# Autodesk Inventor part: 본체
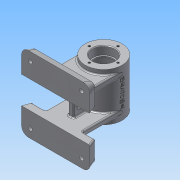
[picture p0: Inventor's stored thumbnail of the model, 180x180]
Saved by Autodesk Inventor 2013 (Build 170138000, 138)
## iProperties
Created: 2016-07
Part Number: 본체
Material: 알루미늄 6061
Document SubType Name: Modeling
Designer: Administrator
Density: 1 g/cm^3
Author: Administrator
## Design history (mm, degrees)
sketch "스케치1"
  geometry: L1 (40, -55)-(-40, -55); L2 (-50, -45)-(-50, 45); L3 (-40, 55)-(40, 55); L4 (50, 45)-(50, -45); L5 (50, -55)-(-50, 55); L6 (-50, -55)-(50, 55); A1 r 10 centre (-40, 45) between (-40, 55) and (-50, 45); A2 r 10 centre (40, 45) between (50, 45) and (40, 55); A3 r 10 centre (40, -45) between (40, -55) and (50, -45); A4 r 10 centre (-40, -45) between (-50, -45) and (-40, -55); 1 further point
  constraints: 12 end point, 8 point on circle, 8 point on line, 8 tangent, 4 centre point, 3 equal radius, 2 midpoint, 2 parallel, 1 horizontal, 1 perpendicular
  dimensions: "d0" = 100 distance of L5.end L6.end; "d1" = 110 distance of L6.start L5.end; "d8" = 10 radius of A1
node "작업 평면1"
sketch "스케치2"
  geometry: L1 (-40.632, 50.632)-(40.632, 50.632); L2 (45.632, 45.632)-(45.632, -45.632); L3 (40.632, -50.632)-(-40.632, -50.632); L4 (-45.632, -45.632)-(-45.632, 45.632); A1 r 5 centre (-40.632, 45.632) between (-40.632, 50.632) and (-45.632, 45.632); A2 r 5 centre (-40.632, -45.632) between (-45.632, -45.632) and (-40.632, -50.632); A3 r 5 centre (40.632, -45.632) between (40.632, -50.632) and (45.632, -45.632); A4 r 5 centre (40.632, 45.632) between (45.632, 45.632) and (40.632, 50.632); 4 further points
  constraints: 8 end point, 8 point on circle, 8 tangent, 6 point on line, 4 centre point, 3 equal radius, 2 parallel, 1 horizontal, 1 perpendicular
  dimensions: "d9" = 5 radius of A1
feature "로프트1" sketch "스케치2" dims "d4" = 0, "d5" = 90 deg, "d6" = 0, "d7" = 90 deg
sketch "스케치3"
  geometry: L1 (-9.368, 5.632)-(-9.368, 95.632) reference; L2 (90.632, 95.632)-(90.632, 5.632) reference; L3 (90.632, 30.632)-(-9.368, 30.632); L4 (-9.368, 30.632)-(-9.368, 70.632); L5 (-9.368, 70.632)-(90.632, 70.632); L6 (90.632, 70.632)-(90.632, 30.632); L7 (90.632, 30.632)-(-9.368, 70.632); L8 (-9.368, 30.632)-(90.632, 70.632); L9 (0.632, 105.632)-(80.632, 105.632) reference; 1 further point
  constraints: 12 end point, 2 midpoint, 2 parallel, 1 horizontal, 1 perpendicular, 1 point on line
  dimensions: "d10" = 35 distance between parallel lines of L9 L5
extrude "돌출2" cut sketch "스케치3" distance "d11" = 12; taper "d12" = 0 deg
sketch "스케치4"
  geometry: L1 (40, 0)-(-40, 0) reference; C1 r 27 at (0, 70); 2 further points
  constraints: 1 centre point, 1 midpoint, 1 vertical alignment
  dimensions: "d13" = 54 diameter of C1; "d15" = 70 distance from line of L1 C1.centre
extrude "돌출3" join sketch "스케치4" stored distance "d16" = 70; taper "d17" = 0 deg
hole "구멍1" diameter "d20" = 28; stored, may be unused: countersink angle "d24" = 90 deg, drill point angle "d26" = 0 deg; dims "d18" = 10, "d19" = 10, "d21" = 6, "d22" = 32, "d23" = 12, "d25" = 2
sketch "스케치5"
  geometry: C1 r 14 at (0, 0) reference; C2 r 22 at (0, 0); 1 further point
  constraints: 1 centre point, 1 coincident
  dimensions: "d27" = 44 diameter of C2
extrude "돌출4" cut sketch "스케치5" distance "d28" = 42; taper "d29" = 0 deg
hole "구멍2" diameter "d32" = 28; stored, may be unused: countersink angle "d36" = 90 deg, drill point angle "d38" = 0 deg; dims "d30" = 10, "d31" = 10, "d33" = 6, "d34" = 32, "d35" = 12, "d37" = 2
chamfer "모따기1" distance "d39" = 1; stored, may be unused: second distance "d40" = 2, angle "d41" = 45 deg
chamfer "모따기2" distance "d42" = 1; stored, may be unused: second distance "d43" = 2, angle "d44" = 45 deg
fillet "모깎기1" dims "d45" = 0.3
fillet "모깎기2" dims "d46" = 2
sketch "스케치6"
  geometry: L1 (-5, 5)-(-5, 30.632) reference; L2 (-5, 30.632)-(86.265, 30.632) reference; L3 (86.265, 30.632)-(86.265, 5) reference; L4 (81.265, 0)-(0, 0) reference; L5 (86.265, 70.632)-(-5, 70.632) reference; L6 (-5, 70.632)-(-5, 96.265) reference; L7 (0, 101.265)-(81.265, 101.265) reference; L8 (86.265, 96.265)-(86.265, 70.632) reference; L9 (67.632, 22.632)-(13.632, 22.632); L10 (13.632, 22.632)-(13.632, 78.632); L11 (13.632, 78.632)-(67.632, 78.632); L12 (67.632, 78.632)-(67.632, 22.632); L13 (67.632, 22.632)-(13.632, 78.632); L14 (13.632, 22.632)-(67.632, 78.632); A1 r 5 centre (0, 5) between (-5, 5) and (0, 0) reference; A2 r 5 centre (81.265, 5) between (81.265, 0) and (86.265, 5) reference; A3 r 5 centre (0, 96.265) between (0, 101.265) and (-5, 96.265) reference; A4 r 5 centre (81.265, 96.265) between (86.265, 96.265) and (81.265, 101.265) reference; 5 further points
  constraints: 12 end point, 8 point on line, 2 midpoint, 2 parallel, 1 horizontal, 1 perpendicular
  dimensions: "d47" = 8 distance between parallel lines of L5 L11; "d48" = 54 distance of L10.end L11.end
extrude "돌출5" join sketch "스케치6" stored distance "d49" = 42; taper "d50" = 0 deg
sketch "스케치7"
  geometry: L1 (86, 23.3)-(86, 34) reference; L2 (86, 34)-(87, 35) reference; L3 (87, 35)-(97, 35) reference; L4 (97, 35)-(97, -35) reference; L5 (97, -35)-(87, -35) reference; L6 (87, -35)-(86, -34) reference; L7 (86, -34)-(86, -23.3) reference; L8 (85.7, -23)-(84, -23) reference; L9 (84, -23)-(84, -21) reference; L10 (84, -21)-(90, -21) reference; L11 (92, -19)-(92, 19) reference; L12 (90, 21)-(84, 21) reference; L13 (84, 21)-(84, 23) reference; L14 (84, 23)-(85.7, 23) reference; L15 (54.3, 23)-(56, 23) reference; L16 (56, 23)-(56, 21) reference; L17 (56, 21)-(50, 21) reference; L18 (48, 19)-(48, -19) reference; L19 (50, -21)-(56, -21) reference; L20 (56, -21)-(56, -23) reference; L21 (56, -23)-(54.3, -23) reference; L22 (54, -23.3)-(54, -34) reference; L23 (54, -34)-(53, -35) reference; L24 (53, -35)-(43, -35) reference; L25 (43, -35)-(43, -28) reference; L26 (43, -28)-(12, -28) reference; L27 (12, -28)-(12, -50.632) reference; L28 (12, -50.632)-(0, -55) reference; L29 (0, -55)-(0, -20) reference; L30 (0, -20)-(43, -20) reference; L31 (43, -20)-(43, 20) reference; L32 (43, 20)-(0, 20) reference; L33 (0, 20)-(0, 55) reference; L34 (0, 55)-(12, 50.632) reference; L35 (12, 50.632)-(12, 28) reference; L36 (12, 28)-(43, 28) reference; L37 (43, 28)-(43, 35) reference; L38 (43, 35)-(53, 35) reference; L39 (53, 35)-(54, 34) reference; L40 (54, 34)-(54, 23.3) reference; L41 (45.5, 20)-(22, 20); L42 (22, 20)-(22, -20); L43 (22, -20)-(45.5, -20); L44 (45.5, -20)-(45.5, 20); A1 r 0.3 centre (85.7, 23.3) between (85.7, 23) and (86, 23.3) reference; A2 r 0.3 centre (85.7, -23.3) between (86, -23.3) and (85.7, -23) reference; A3 r 2 centre (90, -19) between (90, -21) and (92, -19) reference; A4 r 2 centre (90, 19) between (92, 19) and (90, 21) reference; A5 r 0.3 centre (54.3, 23.3) between (54, 23.3) and (54.3, 23) reference; A6 r 2 centre (50, 19) between (50, 21) and (48, 19) reference; A7 r 2 centre (50, -19) between (48, -19) and (50, -21) reference; A8 r 0.3 centre (54.3, -23.3) between (54.3, -23) and (54, -23.3) reference; 1 further point
  constraints: 8 end point, 2 parallel, 1 horizontal, 1 perpendicular, 1 point on line
  dimensions: "d51" = 21 distance between parallel lines of L42 L31
extrude "돌출6" join sketch "스케치7" stored distance "d52" = 8; taper "d53" = 0 deg
sketch "스케치8"
  geometry: L1 (-8, 35.5)-(8, 35.5); L2 (8, 28.5)-(-8, 28.5); L3 (45, 0)-(20, 0) reference; A1 r 3.5 centre (-8, 32) between (-8, 35.5) and (-8, 28.5); A2 r 3.5 centre (8, 32) between (8, 28.5) and (8, 35.5); 3 further points
  constraints: 4 end point, 4 point on circle, 3 tangent, 2 centre point, 2 midpoint, 2 vertical alignment, 1 horizontal alignment
  dimensions: "d54" = 7 diameter of A1; "d55" = 7 diameter of A2; "d56" = 23 dimension on A2 A1; "d57" = 32 distance from line of L3 A1.centre
extrude "돌출7" cut sketch "스케치8" stored distance "d58" = 8; taper "d59" = 0 deg
fillet "모깎기3" dims "d60" = 2
fillet "모깎기4" dims "d61" = 2
fillet "모깎기5" dims "d62" = 2
sketch "스케치9"
  geometry: L1 (78.063, 6.732)-(3.063, 6.732); L2 (3.063, 6.732)-(3.063, 91.732); L3 (3.063, 91.732)-(78.063, 91.732); L4 (78.063, 91.732)-(78.063, 6.732); L5 (78.063, 6.732)-(3.063, 91.732); L6 (3.063, 6.732)-(78.063, 91.732); 5 further points
  constraints: 12 end point, 4 coincident, 2 midpoint, 2 parallel, 1 horizontal, 1 perpendicular
  dimensions: "d63" = 75 distance of L2.end L3.end; "d64" = 85 distance of L1.end L2.end
hole "구멍3" sketch "스케치9" at (3.063, 91.732), (3.063, 6.732), (78.063, 6.732), (78.063, 91.732) diameter "d65" = 6; stored, may be unused: countersink angle "d69" = 90 deg, drill point angle "d71" = 0 deg; dims "d66" = 6, "d67" = 10, "d68" = 4, "d70" = 2
sketch "스케치10" dims "d72" = 42
  geometry: C1 r 17 at (0, 0) reference; 3 further points
  constraints: 2 vertical alignment, 1 coincident, 2 other
hole "구멍4" sketch "스케치10" at (0, 21) diameter "d73" = 3.242; stored, may be unused: countersink angle "d77" = 90 deg, drill point angle "d79" = 118 deg; dims "d74" = 8, "d75" = 32, "d76" = 2, "d78" = 10
node "작업 평면2"
sketch "스케치11"
  geometry: L1 (-13, 90)-(-67, 90) reference; L2 (10, 100)-(10, 75) reference; C1 r 5 at (-40, 68); 1 further point
  constraints: 1 centre point
  dimensions: "d84" = 10 diameter of C1; "d85" = 22 distance from line of L1 C1.centre; "d86" = 50 distance from line of L2 C1.centre
extrude "돌출8" join sketch "스케치11" stored distance "d87" = 8; taper "d88" = 0 deg
hole "구멍5" diameter "d91" = 5.188; stored, may be unused: countersink angle "d95" = 90 deg, drill point angle "d97" = 118 deg; dims "d89" = 10, "d90" = 10, "d92" = 8, "d93" = 32, "d94" = 2, "d96" = 10
sketch "스케치12"
  geometry: L1 (4, 26.5)-(4, 22) reference; L2 (4, 22)-(-4, 22) reference; L3 (-4, 22)-(-4, 26.5) reference; L4 (-2, 28.5)-(2, 28.5) reference; L5 (-4, 37.5)-(-4, 43.298) reference; L6 (4, 43.298)-(4, 37.5) reference; L7 (2, 35.5)-(-2, 35.5) reference; L8 (0, 70)-(0, 28.5); L9 (0, 70)-(-15.898, 44.559); C1 r 22 at (0, 70) reference; A1 r 2 centre (-2, 26.5) between (-2, 28.5) and (-4, 26.5) reference; A2 r 2 centre (2, 26.5) between (4, 26.5) and (2, 28.5) reference; A3 r 27 centre (0, 70) between (4, 43.298) and (-4, 43.298) reference; A4 r 2 centre (2, 37.5) between (2, 35.5) and (4, 37.5) reference; A5 r 2 centre (-2, 37.5) between (-4, 37.5) and (-2, 35.5) reference; 1 further point
  constraints: 4 end point, 1 midpoint
  dimensions: "d99" = 30 distance of L8.start L9.end; "d100" = 32 deg angle of L9 L8
  node "절단 모서리 투영3"
node "작업 평면3"
sketch "스케치13"
  geometry: C1 r 6 at (0, 0); 1 further point
  constraints: 1 centre point
  dimensions: "d101" = 12 diameter of C1
extrude "돌출9" join sketch "스케치13" stored distance "d103" = 8; taper "d104" = 0 deg
sketch "스케치14"
  geometry: C1 r 6 at (0, 0) reference; 1 further point
hole "구멍6" sketch "스케치14" at (0, 0) diameter "d105" = 5.188; stored, may be unused: countersink angle "d109" = 90 deg, drill point angle "d111" = 118 deg; dims "d106" = 8, "d107" = 32, "d108" = 2, "d110" = 10
node "작업 평면4"
sketch "스케치15"
  geometry: L1 (-58, 49.232)-(-58, 29.464) reference; L2 (-56, 26)-(0, 26) reference; L3 (0, 26)-(0, 35) reference; L4 (-70, 55)-(-59.316, 51.111) reference; L5 (-70, 20)-(-70, 55) reference; L6 (-59.464, 20)-(-70, 20) reference; L7 (-56, 26)-(-56, 22) reference; L8 (0, 22)-(0, 26) reference; L9 (0, -22)-(0, 22) reference; L10 (0, -26)-(0, -22) reference; L11 (0, -35)-(0, -26) reference; L12 (-56, 22)-(0, 22) reference; L13 (-56, -22)-(0, -22) reference; L14 (-56, -22)-(-56, -26) reference; L15 (-56, -26)-(0, -26) reference; L16 (-70, -20)-(-59.464, -20) reference; L17 (-70, -55)-(-70, -20) reference; L18 (-59.316, -51.111)-(-70, -55) reference; L19 (-58, -29.464)-(-58, -49.232) reference; A1 r 2 centre (-60, 49.232) between (-58, 49.232) and (-59.316, 51.111) reference; A2 r 2 centre (-60, -49.232) between (-59.316, -51.111) and (-58, -49.232) reference; 3 further points
  constraints: 1 coincident, 1 midpoint, 5 other
feature "엠보싱1" sketch "스케치15" dims "d0" = 100, "d1" = 110, "d8" = 10, "d112" = 0.5, "d113" = 0
fillet "모깎기6" dims "d114" = 2
node "솔리드2"
mirror "대칭1"
pattern_circular "원형 패턴1" dims angle "d81" = 360 deg
mirror "대칭2"
node "절단 모서리 투영1"
node "절단 모서리 투영2"
node "절단 모서리 투영4"
